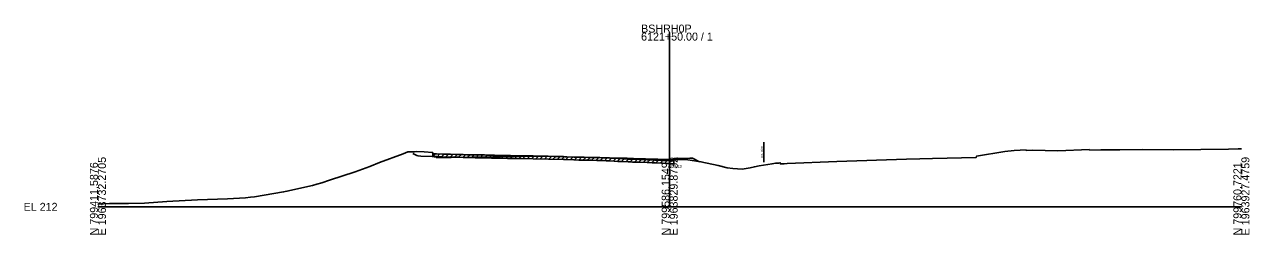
# Model space of a CAD drawing. Extents: x -26 to 1986619, y -10 to 827846.
# Drawn here: x -25.7 to 402.8, y 1490.3 to 1563.8 of the extents above; entities that cross this region are included whole.
import ezdxf

# ---------------------------------------------------------------- set-up
doc = ezdxf.new("R2010")
doc.units = 0
for name, color, linetype in [('Default', 7, 'Continuous'), ('RD_EX_Road', 7, 'Continuous'), ('RD_PD_ALT5_LnLine', 7, 'Continuous'), ('RD_PD_ALT5_TrvlWay', 7, 'Continuous'), ('RD_PD_PaveDit', 7, 'Continuous'), ('RD_Sketch2', 7, 'Continuous'), ('RD_XS_ExRW', 7, 'Continuous')]:
    doc.layers.add(name, color=color, linetype=linetype)

msp = doc.modelspace()

# ---------------------------------------------------------------- linework, layer by layer
at = {"layer": 'RD_EX_Road'}
for p, q in [((200, 1500), (200, 1561)), ((0, 1500), (200, 1500)), ((200, 1500), (400, 1500))]:
    msp.add_line(p, q, dxfattribs=at)
at = {"layer": 'RD_PD_ALT5_LnLine'}
msp.add_lwpolyline([(0, 1500.95), (4.07, 1501.17), (6.92, 1501.13), (10.71, 1501.14), (16.3, 1501.3), (24.11, 1501.83), (34.8, 1502.49), (45.28, 1502.8), (51.64, 1503.16), (53.42, 1503.37), (54.76, 1503.49), (64.95, 1505.21), (66.12, 1505.44), (75.09, 1507.52), (76.6, 1507.91), (78.35, 1508.4), (81.01, 1509.29), (89.96, 1512.28), (95.12, 1514.08), (98.52, 1515.48), (106.78, 1518.57), (108.38, 1519.2), (110.7, 1519.28), (111.49, 1519.32), (114.07, 1519.21), (117.07, 1519.08), (117.18, 1518.63), (117.6, 1518.51), (118.47, 1518.56), (120.48, 1518.49), (122.28, 1518.42), (123.3, 1518.39), (125.53, 1518.35), (126.17, 1518.34), (127.78, 1518.29), (129.06, 1518.26), (130.65, 1518.23), (131.93, 1518.21), (133.57, 1518.18), (134.79, 1518.17), (135.23, 1518.16), (136.04, 1518.14), (136.75, 1518.12), (137.63, 1518.09), (138.78, 1518.05), (140.86, 1518), (143.31, 1517.95), (144.27, 1517.94), (146.2, 1517.91), (147.52, 1517.9), (148.21, 1517.91), (152.27, 1517.81), (162.81, 1517.57), (163.31, 1517.54), (166.49, 1517.42), (168.21, 1517.38), (169.15, 1517.36), (170.05, 1517.34), (171.62, 1517.3), (172.04, 1517.29), (172.48, 1517.29), (174.47, 1517.27), (175.02, 1517.27), (175.57, 1517.25), (176.75, 1517.18), (177.75, 1517.13), (179.02, 1517.06), (180.6, 1516.98), (181.86, 1516.91), (183.45, 1516.82), (185.45, 1516.73), (186.3, 1516.7), (186.98, 1516.67), (189.17, 1516.58), (192.09, 1516.48), (193.91, 1516.41), (194.91, 1516.37), (197.18, 1516.26), (197.76, 1516.23), (198.37, 1516.2), (200.23, 1516.12), (200.63, 1516.1), (201.5, 1516.03), (201.55, 1516.52), (206.35, 1516.49), (210.96, 1515.78), (217, 1514.49), (220.09, 1513.62), (222.13, 1513.46), (225.33, 1513.19), (228.2, 1513.71), (229.66, 1514.02), (231.28, 1514.3), (235.8, 1515.1), (237.07, 1515.26), (238.17, 1515.3), (238.61, 1515.45), (238.72, 1515), (240.07, 1515.08), (241.07, 1515.12), (258.49, 1515.91), (282.86, 1516.66), (287.56, 1516.83), (291.93, 1516.91), (307.24, 1517.33), (307.35, 1517.78), (317.29, 1519.41), (320.57, 1519.76), (324.68, 1519.91), (324.7, 1519.77), (326.98, 1519.88), (335.82, 1519.65), (346.86, 1520.03), (346.89, 1519.89), (350.79, 1519.97), (356.95, 1519.99), (357.47, 1519.99), (365.38, 1520.07), (376.16, 1520.01), (395.53, 1520.23), (398.92, 1520.32), (400, 1520.33)], dxfattribs=at)
at = {"layer": 'RD_PD_PaveDit'}
for p, q in [((117.18, 1517.63), (117.18, 1518.63)), ((117.18, 1517.63), (118.1, 1518.54)), ((117.18, 1517.63), (117.6, 1517.51)), ((117.6, 1517.51), (118.47, 1517.56)), ((118.47, 1517.56), (120.48, 1517.49)), ((118.68, 1517.55), (119.65, 1518.52)), ((120.18, 1517.5), (121.15, 1518.46)), ((120.48, 1517.49), (122.28, 1517.42)), ((121.68, 1517.45), (122.65, 1518.41)), ((122.28, 1517.42), (123.3, 1517.39)), ((123.18, 1517.4), (124.16, 1518.38)), ((123.3, 1517.39), (125.53, 1517.35)), ((124.68, 1517.37), (125.66, 1518.35)), ((125.53, 1517.35), (126.17, 1517.34)), ((126.17, 1517.34), (127.78, 1517.29)), ((126.18, 1517.34), (127.15, 1518.31)), ((127.68, 1517.29), (128.66, 1518.27)), ((127.78, 1517.29), (129.06, 1517.26)), ((129.06, 1517.26), (130.65, 1517.23)), ((129.18, 1517.26), (130.16, 1518.24)), ((130.65, 1517.23), (131.93, 1517.21)), ((130.68, 1517.23), (131.66, 1518.21)), ((131.93, 1517.21), (133.57, 1517.18)), ((132.18, 1517.2), (133.17, 1518.19)), ((133.57, 1517.18), (134.79, 1517.17)), ((133.68, 1517.18), (134.67, 1518.17)), ((134.79, 1517.17), (135.23, 1517.16)), ((135.18, 1517.16), (136.16, 1518.14)), ((135.23, 1517.16), (136.04, 1517.14)), ((136.04, 1517.14), (136.75, 1517.12)), ((136.68, 1517.12), (137.65, 1518.09)), ((136.75, 1517.12), (137.63, 1517.09)), ((137.63, 1517.09), (138.78, 1517.05)), ((138.18, 1517.07), (139.15, 1518.05)), ((138.78, 1517.05), (140.86, 1517)), ((139.68, 1517.03), (140.66, 1518.01)), ((141.18, 1517), (142.16, 1517.98)), ((142.68, 1516.96), (143.66, 1517.95)), ((144.18, 1516.94), (145.17, 1517.92)), ((145.68, 1516.92), (146.67, 1517.9)), ((147.18, 1516.9), (148.19, 1517.91)), ((148.68, 1516.9), (149.66, 1517.87)), ((150.18, 1516.86), (151.16, 1517.84)), ((151.68, 1516.83), (152.66, 1517.81)), ((153.18, 1516.79), (154.16, 1517.77)), ((154.68, 1516.76), (155.66, 1517.74)), ((156.18, 1516.72), (157.16, 1517.7)), ((157.68, 1516.69), (158.66, 1517.67)), ((159.18, 1516.65), (160.16, 1517.63)), ((160.68, 1516.62), (161.66, 1517.6)), ((162.18, 1516.59), (163.15, 1517.55)), ((163.68, 1516.53), (164.64, 1517.49)), ((165.18, 1516.47), (166.14, 1517.43)), ((166.68, 1516.42), (167.66, 1517.39)), ((168.18, 1516.38), (169.16, 1517.36)), ((169.68, 1516.35), (170.66, 1517.33)), ((171.18, 1516.31), (172.16, 1517.29)), ((172.68, 1516.29), (173.67, 1517.28)), ((174.18, 1516.27), (175.17, 1517.26)), ((175.68, 1516.24), (176.63, 1517.19)), ((177.18, 1516.16), (178.13, 1517.11)), ((178.68, 1516.08), (179.63, 1517.03)), ((140.86, 1517), (143.31, 1516.95)), ((143.31, 1516.95), (144.27, 1516.94)), ((144.27, 1516.94), (146.2, 1516.91)), ((146.2, 1516.91), (147.52, 1516.9)), ((147.52, 1516.9), (148.21, 1516.91)), ((148.21, 1516.91), (152.27, 1516.81)), ((152.27, 1516.81), (162.81, 1516.57)), ((162.81, 1516.57), (163.31, 1516.54)), ((163.31, 1516.54), (166.49, 1516.42)), ((166.49, 1516.42), (168.21, 1516.38)), ((168.21, 1516.38), (169.15, 1516.36)), ((169.15, 1516.36), (170.05, 1516.34)), ((170.05, 1516.34), (171.62, 1516.3)), ((171.62, 1516.3), (172.04, 1516.29)), ((172.04, 1516.29), (172.48, 1516.29)), ((172.48, 1516.29), (174.47, 1516.27)), ((174.47, 1516.27), (175.02, 1516.27)), ((175.02, 1516.27), (175.57, 1516.25)), ((175.57, 1516.25), (176.75, 1516.18)), ((176.75, 1516.18), (177.75, 1516.13)), ((177.75, 1516.13), (179.02, 1516.06)), ((179.02, 1516.06), (180.6, 1515.98)), ((180.18, 1516), (181.13, 1516.95)), ((180.6, 1515.98), (181.86, 1515.91)), ((181.68, 1515.92), (182.63, 1516.87)), ((181.86, 1515.91), (183.45, 1515.82)), ((183.18, 1515.84), (184.14, 1516.79)), ((183.45, 1515.82), (185.45, 1515.73)), ((184.68, 1515.77), (185.64, 1516.73)), ((185.45, 1515.73), (186.3, 1515.7)), ((186.18, 1515.7), (187.14, 1516.66)), ((186.3, 1515.7), (186.98, 1515.67)), ((186.98, 1515.67), (189.17, 1515.58)), ((187.68, 1515.64), (188.64, 1516.6)), ((189.17, 1515.58), (192.09, 1515.48)), ((189.18, 1515.58), (190.15, 1516.55)), ((190.68, 1515.53), (191.65, 1516.5)), ((192.09, 1515.48), (193.91, 1515.41)), ((192.18, 1515.48), (193.14, 1516.44)), ((193.68, 1515.42), (194.64, 1516.38)), ((193.91, 1515.41), (194.91, 1515.37)), ((194.91, 1515.37), (197.18, 1515.26)), ((195.18, 1515.35), (196.14, 1516.31)), ((196.68, 1515.28), (197.64, 1516.24)), ((197.18, 1515.26), (197.76, 1515.23)), ((197.76, 1515.23), (198.37, 1515.2)), ((198.18, 1515.21), (199.14, 1516.17)), ((198.37, 1515.2), (200.23, 1515.12)), ((199.68, 1515.14), (200.64, 1516.1)), ((200.23, 1515.12), (200.63, 1515.1)), ((200.63, 1515.1), (201.45, 1515.04)), ((201.45, 1516.04), (201.45, 1515.04))]:
    msp.add_line(p, q, dxfattribs=at)
at = {"layer": 'RD_Sketch2'}
msp.add_lwpolyline([(110.19, 1518.71), (111.55, 1518.02), (111.99, 1517.8), (112.99, 1517.78), (116.87, 1517.68), (117.99, 1517.65), (118.49, 1517.64), (118.57, 1517.14), (119.69, 1517.22), (119.99, 1517.24), (123.07, 1517.3), (123.57, 1517.31), (152.56, 1517.73), (155.12, 1517.77), (172.93, 1517.32), (185.14, 1517.01), (186.68, 1516.97), (187.35, 1516.95), (200.06, 1516.57), (201.48, 1516.46), (201.56, 1516.96), (202.06, 1516.96), (202.66, 1516.96), (207.04, 1517.03), (208.04, 1517.04), (210.48, 1515.81)], dxfattribs=at)
at = {"layer": 'RD_XS_ExRW'}
msp.add_line((232.93, 1515.59), (232.93, 1522.59), dxfattribs=at)

# ---------------------------------------------------------------- texts
at = {"layer": 'Default'}
msp.add_text('-', height=0.0001, dxfattribs=at).set_placement((0, 1500))
at = {"layer": 'RD_EX_Road'}
for s, p in [('6121+50.00 / 1', (190, 1558.2)), ('BSHRH0P', (190, 1561)), ('EL 212', (-26, 1498.6))]:
    msp.add_text(s, height=2.8, dxfattribs=at).set_placement(p)
for s, p in [('E 1963732.2705', (2.8, 1490)), ('E 1963829.8732', (202.8, 1490)), ('E 1963927.4759', (402.8, 1490)), ('N 799411.5876', (0, 1490)), ('N 799586.1549', (200, 1490)), ('N 799760.7221', (400, 1490))]:
    msp.add_text(s, height=2.8, rotation=90, dxfattribs=at).set_placement(p)
at = {"layer": 'RD_PD_ALT5_TrvlWay'}
msp.add_text('228.13', height=1, dxfattribs=at).set_placement((200, 1513.63))
at = {"layer": 'RD_XS_ExRW'}
msp.add_text('EX. R/W ', height=0.75, rotation=90, dxfattribs=at).set_placement((232.65, 1517.27))

doc.saveas('drawing.dxf')
